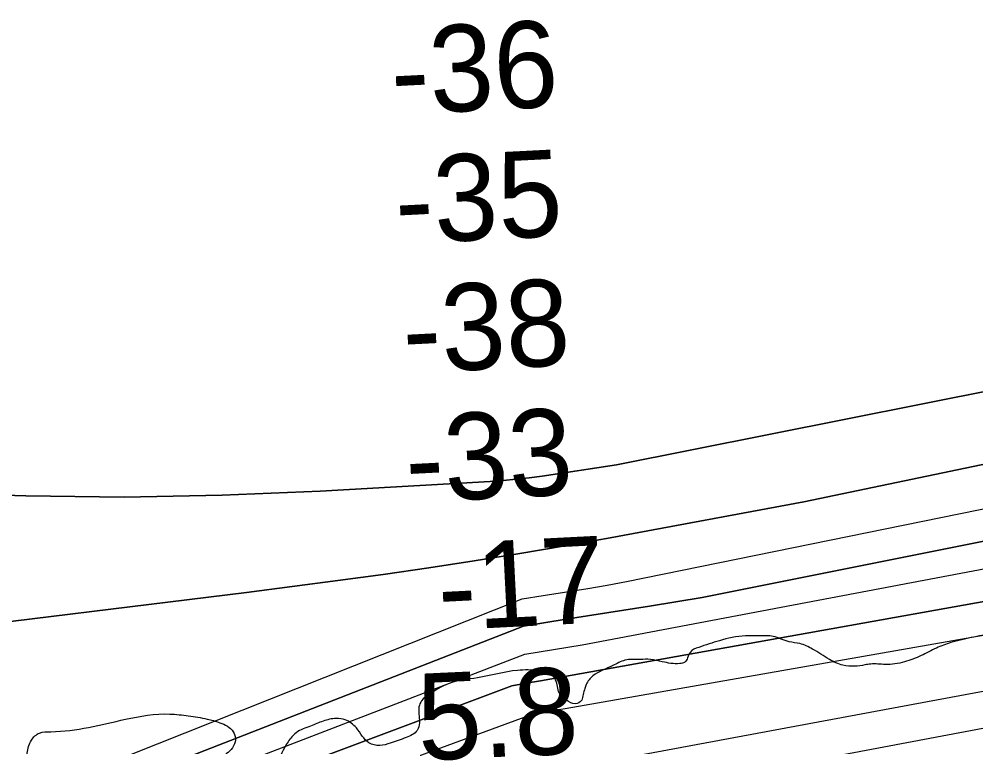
# Model space of a CAD drawing. Extents: x 3445503 to 3483459, y 540493 to 566012.
# Drawn here: x 3461717 to 3462457, y 550217 to 550780 of the extents above; entities that cross this region are included whole.
import ezdxf

# ---------------------------------------------------------------- set-up
doc = ezdxf.new("R2010")
doc.units = 0
for name, color, linetype in [('V-RIVR-EDGE', 7, 'Continuous'), ('V-RIVR-RANG', 7, 'Continuous'), ('V-TOPO-DPTH', 7, 'Continuous'), ('V-TOPO-MINR', 7, 'Continuous'), ('V-TOPO-WATR', 7, 'Continuous')]:
    doc.layers.add(name, color=color, linetype=linetype)

msp = doc.modelspace()

# ---------------------------------------------------------------- linework, layer by layer
at = {"layer": 'V-RIVR-EDGE'}
for points in [[(3464240.76, 550568.22), (3464194.17, 550562.43), (3464170.52, 550559.36), (3464160.09, 550560.08), (3464152.1, 550562.88), (3464144.1, 550559.77), (3464137.84, 550557.01), (3464132.61, 550553.54), (3464120.44, 550551.84), (3464111.75, 550549.77), (3464091.59, 550551.21), (3464071.09, 550554.74), (3464053.36, 550554.43), (3464011.29, 550553.84), (3463955.31, 550548.07), (3463935.83, 550543.95), (3463926.09, 550539.11), (3463922.24, 550531.47), (3463921.87, 550521.39), (3463920.11, 550511.66), (3463915.92, 550505.41), (3463903.4, 550501.97), (3463893.32, 550502.69), (3463886.03, 550507.57), (3463876.67, 550518.02), (3463871.82, 550526.73), (3463860.71, 550532.66), (3463854.46, 550531.98), (3463843.32, 550529.23), (3463836.02, 550528.9), (3463822.12, 550529.63), (3463812.04, 550532.09), (3463805.09, 550530.71), (3463800.56, 550526.9), (3463796.04, 550525.17), (3463792.21, 550525.18), (3463785.97, 550530.07), (3463777.63, 550533.91), (3463755.74, 550536.75), (3463735.23, 550537.84), (3463700.81, 550536.88), (3463663.61, 550531.76), (3463638.57, 550527.65), (3463632.65, 550525.23), (3463623.61, 550524.21), (3463615.62, 550525.62), (3463608.32, 550525.29), (3463599.27, 550522.88), (3463591.95, 550516.29), (3463587.08, 550514.57), (3463580.14, 550517.02), (3463569.72, 550522.26), (3463566.94, 550522.26), (3463563.11, 550519.84), (3463559.63, 550517.07), (3463551.28, 550516.39), (3463543.64, 550517.8), (3463539.47, 550521.29), (3463535.66, 550524.43), (3463531.49, 550525.48), (3463519.32, 550525.16), (3463508.2, 550524.15), (3463500.53, 550518.95), (3463474.8, 550516.23), (3463463.33, 550517.31), (3463452.21, 550516.64), (3463438.64, 550513.89), (3463430.99, 550511.48), (3463420.56, 550511.15), (3463410.13, 550511.18), (3463402.49, 550515.72), (3463395.9, 550519.56), (3463391.38, 550520.61), (3463385.13, 550520.98), (3463379.21, 550519.95), (3463372.6, 550516.84), (3463363.55, 550509.9), (3463354.14, 550504.02), (3463345.1, 550501.61), (3463333.62, 550497.46), (3463323.88, 550496.1), (3463316.23, 550496.81), (3463311.37, 550496.82), (3463301.28, 550495.11), (3463290.85, 550493.05), (3463275.2, 550490.31), (3463253.64, 550487.93), (3463230.69, 550485.9), (3463201.83, 550482.15), (3463171.58, 550478.75), (3463158.36, 550475.65), (3463147.22, 550471.85), (3463129.49, 550468.77), (3463117.67, 550468.8), (3463103.06, 550466.4), (3463077.33, 550462.99), (3463057.51, 550460.26), (3463023.42, 550453.39), (3462976.47, 550444.81), (3462928.47, 550432.76), (3462869.67, 550415.18), (3462853.67, 550410), (3462833.15, 550404.84), (3462827.24, 550405.2), (3462820.63, 550404.87), (3462811.59, 550404.55), (3462801.16, 550403.53), (3462795.59, 550398.68), (3462790.01, 550393.82), (3462786.52, 550387.92), (3462785.12, 550381.32), (3462781.98, 550377.85), (3462773.63, 550376.48), (3462765.98, 550375.81), (3462759.04, 550378.26), (3462750.36, 550384.88), (3462742.03, 550389.08), (3462735.08, 550391.87), (3462711.45, 550392.98), (3462677.71, 550386.45), (3462657.53, 550380.94), (3462643.26, 550372.98), (3462626.55, 550362.25), (3462614.01, 550351.85), (3462607.03, 550342.13), (3462601.8, 550335.89), (3462595.88, 550330.34), (3462589.61, 550327.92), (3462581.96, 550326.2), (3462575.36, 550326.91), (3462565.98, 550329.72), (3462554.17, 550333.92), (3462549.31, 550335.32), (3462542.01, 550334.64), (3462530.52, 550330.15), (3462505.46, 550317.7), (3462485.98, 550310.1), (3462462.67, 550303.9), (3462437.28, 550298.05), (3462426.14, 550293.91), (3462414.31, 550288.03), (3462401.43, 550283.19), (3462386.48, 550281.15), (3462375.36, 550281.52), (3462370.84, 550280.84), (3462362.84, 550279.81), (3462353.8, 550280.53), (3462343.39, 550285.08), (3462330.19, 550293.1), (3462320.47, 550297.3), (3462312.13, 550298.71), (3462299.98, 550302.91), (3462289.2, 550303.29), (3462278.42, 550303.31), (3462258.25, 550299.54), (3462242.25, 550294.36), (3462235.63, 550290.56), (3462231.44, 550282.92), (3462227.62, 550281.89), (3462214.06, 550283.31), (3462205.03, 550285.07), (3462197.03, 550285.09), (3462185.21, 550284.42), (3462175.81, 550280.28), (3462160.5, 550272.32), (3462155.27, 550265.73), (3462154.22, 550262.6), (3462152.82, 550258.08), (3462151.76, 550253.57), (3462146.89, 550250.8), (3462139.94, 550253.6), (3462134.39, 550259.17), (3462131.64, 550269.26), (3462126.44, 550274.14), (3462118.79, 550276.25), (3462102.11, 550276.63), (3462071.15, 550270.8), (3462048.55, 550266.34), (3462033.93, 550258.03), (3462028, 550253.18), (3462025.91, 550248.32), (3462025.89, 550242.76), (3462026.22, 550236.15), (3462024.47, 550230.24), (3462016.11, 550224.7), (3462003.75, 550220.36)], [(3462003.75, 550220.36), (3461995.59, 550218.5), (3461987.25, 550220.6), (3461977.55, 550232.1), (3461968.87, 550238.38), (3461961.92, 550239.44), (3461951.83, 550237.38), (3461942.09, 550233.58), (3461930.95, 550228.39), (3461924.68, 550221.45), (3461915.25, 550203.75), (3461912.11, 550199.93), (3461906.89, 550198.2), (3461903.06, 550195.43), (3461899.93, 550192.31), (3461893.98, 550179.12), (3461884.55, 550158.98), (3461876.18, 550149.26), (3461867.47, 550142.33), (3461855.29, 550137.15), (3461827.11, 550127.83), (3461811.47, 550129.26), (3461801.39, 550128.24), (3461788.17, 550124.11), (3461754.41, 550110.28), (3461738.75, 550103.37), (3461726.23, 550099.92), (3461715.1, 550099.26), (3461705.71, 550096.15), (3461691.09, 550090.62)], [(3461782.02, 550168.62), (3461757, 550174.24), (3461737.21, 550180.9), (3461728.88, 550187.52), (3461727.15, 550193.09), (3461723.03, 550212.56), (3461726.18, 550222.64), (3461732.46, 550228.18), (3461741.15, 550229.21), (3461798.88, 550238.8), (3461833.3, 550242.88), (3461847.55, 550241.46), (3461862.15, 550238.99), (3461871.88, 550236.18), (3461882.29, 550229.2), (3461884.01, 550222.94), (3461883.31, 550219.82), (3461879.47, 550214.26), (3461869.37, 550207.34)]]:
    msp.add_spline(points, degree=3, dxfattribs=at)
at = {"layer": 'V-TOPO-DPTH'}
for points in [[(3460826.61, 549947.36), (3461361.19, 550029.12), (3461371.44, 550030.75), (3461381.68, 550032.46), (3461391.9, 550034.29), (3461402.1, 550036.21), (3462106.66, 550310.78), (3462139.67, 550316.11), (3462172.7, 550321.33), (3462204.17, 550326.22), (3462244.98, 550332.83), (3462841.69, 550452.28), (3463001.94, 550483.79), (3463015.58, 550486.53), (3463029.21, 550489.34), (3463042.81, 550492.26), (3463056.4, 550495.25), (3463082.34, 550501.06), (3463096.66, 550504.41), (3463110.93, 550507.93), (3463641.78, 550595.69), (3463666.23, 550597.32), (3463690.7, 550598.76), (3463850.95, 550607.3)], [(3463850.95, 550607.3), (3463690.7, 550598.76), (3463666.23, 550597.32), (3463641.78, 550595.69), (3463110.93, 550507.93), (3463096.66, 550504.41), (3463082.34, 550501.06), (3463056.4, 550495.25), (3463042.81, 550492.26), (3463029.21, 550489.34), (3463015.58, 550486.53), (3463001.94, 550483.79), (3462841.69, 550452.28), (3462244.98, 550332.83), (3462204.17, 550326.22), (3462172.7, 550321.33), (3462139.67, 550316.11), (3462106.66, 550310.78), (3461402.1, 550036.21), (3461391.9, 550034.29), (3461381.68, 550032.46), (3461371.44, 550030.75), (3461361.19, 550029.12), (3460826.61, 549947.36)], [(3463007.24, 550600.48), (3462178.76, 550435.51), (3462121.15, 550426.86), (3462111.16, 550425.5), (3462101.14, 550424.32), (3462091.1, 550423.42), (3462081.04, 550422.71), (3461949.53, 550415.25), (3461873.7, 550412.14), (3461797.86, 550410.6), (3461722.01, 550411.43), (3461646.15, 550413.83), (3461371.47, 550426.82), (3461359.67, 550427.42), (3461347.87, 550428.08), (3461336.08, 550428.82), (3461324.3, 550429.61), (3461297.72, 550431.5), (3461272.66, 550433.43), (3461247.62, 550435.58), (3461222.6, 550438.03), (3461197.61, 550440.69)], [(3463007.24, 550600.48), (3462178.76, 550435.51), (3462121.15, 550426.86), (3462111.16, 550425.5), (3462101.14, 550424.32), (3462091.1, 550423.42), (3462081.04, 550422.71), (3461949.53, 550415.25), (3461873.7, 550412.14), (3461797.86, 550410.6), (3461722.01, 550411.43), (3461646.15, 550413.83), (3461371.47, 550426.82), (3461359.67, 550427.42), (3461347.87, 550428.08), (3461336.08, 550428.82), (3461324.3, 550429.61), (3461297.72, 550431.5), (3461272.66, 550433.43), (3461247.62, 550435.58), (3461222.6, 550438.03), (3461197.61, 550440.69)], [(3460796.68, 549887), (3461333.7, 549993.24), (3461359, 549997.61), (3461384.27, 550002.09), (3461409.51, 550006.76), (3462097.68, 550264.71), (3462108.77, 550266.64), (3462119.87, 550268.5), (3462864.92, 550401.86), (3462898.89, 550408.81), (3462949.81, 550419.38), (3462966.81, 550422.78), (3462983.82, 550426.13), (3462991.05, 550427.53), (3463642.04, 550570.24), (3463653.7, 550570.91), (3463665.37, 550571.48), (3464200.45, 550593.79)], [(3464200.45, 550593.79), (3463665.37, 550571.48), (3463653.7, 550570.91), (3463642.04, 550570.24), (3462991.05, 550427.53), (3462983.82, 550426.13), (3462966.81, 550422.78), (3462949.81, 550419.38), (3462898.89, 550408.81), (3462864.92, 550401.86), (3462119.87, 550268.5), (3462108.77, 550266.64), (3462097.68, 550264.71), (3461409.51, 550006.76), (3461384.27, 550002.09), (3461359, 549997.61), (3461333.7, 549993.24), (3460796.68, 549887)], [(3459211.38, 549345.72), (3459924.71, 549586.06), (3459936.94, 549589.12), (3460800.63, 549811.2), (3461414.15, 549976.77), (3461441.4, 549981.97), (3462062.16, 550182.04), (3462087.24, 550188.76), (3462112.44, 550194.95), (3462137.83, 550200.35), (3463061.3, 550371.99), (3463612.81, 550520.65), (3463627.71, 550525.32), (3463642.71, 550529.62), (3463657.86, 550533.37), (3463673.11, 550536.73), (3463688.48, 550539.38), (3463703.91, 550541.45), (3463719.44, 550542.63), (3463735.03, 550543.24)], [(3462841.11, 550514.77), (3462323.66, 550406.99), (3462173.91, 550379.16), (3462138.91, 550372.86), (3462103.86, 550366.84), (3462068.74, 550361.22), (3462033.58, 550355.87), (3461998.36, 550350.85), (3461963.13, 550345.99), (3461927.86, 550341.36), (3461892.57, 550336.89), (3461380.43, 550273.82), (3461370.85, 550272.55), (3461361.3, 550271.17), (3461351.77, 550269.6), (3461342.26, 550267.92), (3461286.68, 550257.57), (3461267.79, 550253.44), (3461249.13, 550248.55), (3461230.8, 550242.51), (3461212.7, 550235.71), (3461194.82, 550228.22)], [(3461194.82, 550228.22), (3461212.7, 550235.71), (3461230.8, 550242.51), (3461249.13, 550248.55), (3461267.79, 550253.44), (3461286.68, 550257.57), (3461342.26, 550267.92), (3461351.77, 550269.6), (3461361.3, 550271.17), (3461370.85, 550272.55), (3461380.43, 550273.82), (3461892.57, 550336.89), (3461927.86, 550341.36), (3461963.13, 550345.99), (3461998.36, 550350.85), (3462033.58, 550355.87), (3462068.74, 550361.22), (3462103.86, 550366.84), (3462138.91, 550372.86), (3462173.91, 550379.16), (3462323.66, 550406.99), (3462841.11, 550514.77)]]:
    msp.add_lwpolyline(points, dxfattribs=at)
at = {"layer": 'V-TOPO-MINR'}
for points in [[(3460826.61, 549947.36), (3461361.19, 550029.12), (3461371.44, 550030.75), (3461381.68, 550032.46), (3461391.9, 550034.29), (3461402.1, 550036.21), (3462106.66, 550310.78), (3462139.67, 550316.11), (3462172.7, 550321.33), (3462204.17, 550326.22), (3462244.98, 550332.83), (3462841.69, 550452.28), (3463001.94, 550483.79), (3463015.58, 550486.53), (3463029.21, 550489.34), (3463042.81, 550492.26), (3463056.4, 550495.25), (3463082.34, 550501.06), (3463096.66, 550504.41), (3463110.93, 550507.93), (3463641.78, 550595.69), (3463666.23, 550597.32), (3463690.7, 550598.76), (3463850.95, 550607.3)], [(3460819.02, 549919.51), (3461347.41, 550011.27), (3461365.2, 550014.22), (3461382.97, 550017.29), (3461400.71, 550020.52), (3461418.43, 550023.87), (3462107.7, 550289.11), (3462129.95, 550292.77), (3462152.21, 550296.35), (3463030.72, 550462.58), (3463057.52, 550468.3), (3463084.29, 550474.15), (3463139.15, 550486.38), (3463641.91, 550582.76), (3463659.88, 550583.88), (3463677.85, 550584.84), (3463985.31, 550599.4)], [(3461197.61, 550440.69), (3461222.6, 550438.03), (3461247.62, 550435.58), (3461272.66, 550433.43), (3461297.72, 550431.5), (3461324.3, 550429.61), (3461336.08, 550428.82), (3461347.87, 550428.08), (3461359.67, 550427.42), (3461371.47, 550426.82), (3461646.15, 550413.83), (3461722.01, 550411.43), (3461797.86, 550410.6), (3461873.7, 550412.14), (3461949.53, 550415.25), (3462081.04, 550422.71), (3462091.1, 550423.42), (3462101.14, 550424.32), (3462111.16, 550425.5), (3462121.15, 550426.86), (3462178.76, 550435.51), (3463007.24, 550600.48)], [(3460773.79, 549852.53), (3461385.57, 549986.88), (3461418.29, 549993.01), (3461451, 549999.24), (3462105.17, 550239.69), (3462107.58, 550240.52), (3462110, 550241.3), (3462112.44, 550242.02), (3462114.9, 550242.69), (3462117.37, 550243.29), (3462119.85, 550243.85), (3462122.35, 550244.34), (3462124.86, 550244.78), (3462129.36, 550245.52), (3462132.54, 550246.04), (3462135.72, 550246.56), (3462138.9, 550247.09), (3463034.12, 550404.13), (3463040.52, 550405.37), (3463046.91, 550406.63), (3463653.21, 550558.59), (3464432.27, 550586.79)], [(3459211.38, 549345.72), (3459924.71, 549586.06), (3459936.94, 549589.12), (3460800.63, 549811.2), (3461414.15, 549976.77), (3461441.4, 549981.97), (3462062.16, 550182.04), (3462087.24, 550188.76), (3462112.44, 550194.95), (3462137.83, 550200.35), (3463061.3, 550371.99), (3463612.81, 550520.65), (3463627.71, 550525.32), (3463642.71, 550529.62), (3463657.86, 550533.37), (3463673.11, 550536.73), (3463688.48, 550539.38), (3463703.91, 550541.45), (3463719.44, 550542.63), (3463735.03, 550543.24)], [(3460771.44, 549971.49), (3461212, 550024.88), (3461254.12, 550030.39), (3461296.23, 550036.04), (3461375.03, 550046.79), (3461377.72, 550047.18), (3461380.4, 550047.6), (3461383.08, 550048.07), (3461385.75, 550048.56), (3461402.47, 550051.81), (3461404.55, 550052.33), (3461406.56, 550053), (3461410.37, 550054.91), (3461411.7, 550056.22), (3462105.63, 550332), (3462122.1, 550334.61), (3462138.59, 550337.17), (3462141.52, 550337.62), (3462156.53, 550340.02), (3462171.51, 550342.55), (3462186.46, 550345.27), (3463031.03, 550517.1)], [(3461194.82, 550228.22), (3461212.7, 550235.71), (3461230.8, 550242.51), (3461249.13, 550248.55), (3461267.79, 550253.44), (3461286.68, 550257.57), (3461342.26, 550267.92), (3461351.77, 550269.6), (3461361.3, 550271.17), (3461370.85, 550272.55), (3461380.43, 550273.82), (3461892.57, 550336.89), (3461927.86, 550341.36), (3461963.13, 550345.99), (3461998.36, 550350.85), (3462033.58, 550355.87), (3462068.74, 550361.22), (3462103.86, 550366.84), (3462138.91, 550372.86), (3462173.91, 550379.16), (3462323.66, 550406.99), (3462841.11, 550514.77)], [(3459155.64, 549293.25), (3459905.81, 549540.06), (3459920.2, 549545.16), (3459934.63, 549550.14), (3459949.08, 549555.05), (3460803.93, 549764.42), (3461388.2, 549956.36), (3461392.75, 549957.21), (3461397.29, 549958.07), (3462102.29, 550164.56), (3462113.64, 550166.95), (3462125.07, 550168.97), (3462136.55, 550170.74), (3463026.5, 550338.47), (3463037.8, 550339.99), (3463049.11, 550341.47), (3463060.43, 550342.92), (3463631.14, 550468.86), (3463643.23, 550470.52), (3463655.39, 550471.51), (3463667.59, 550472.05), (3464480.31, 550485.96)]]:
    msp.add_lwpolyline(points, dxfattribs=at)
at = {"layer": 'V-TOPO-WATR'}
msp.add_lwpolyline([(3460796.68, 549887), (3461333.7, 549993.24), (3461359, 549997.61), (3461384.27, 550002.09), (3461409.51, 550006.76), (3462097.68, 550264.71), (3462108.77, 550266.64), (3462119.87, 550268.5), (3462864.92, 550401.86), (3462898.89, 550408.81), (3462949.81, 550419.38), (3462966.81, 550422.78), (3462983.82, 550426.13), (3462991.05, 550427.53), (3463642.04, 550570.24), (3463653.7, 550570.91), (3463665.37, 550571.48), (3464200.45, 550593.79)], dxfattribs=at)

# ---------------------------------------------------------------- texts
at = {"layer": 'V-RIVR-RANG'}
for s, rotation, p in [('-36', 2.89644, (3462005.56, 550706.07)), ('-35', 2.89644, (3462008.79, 550606.1)), ('-38', 2.89644, (3462014.65, 550506.27)), ('-33', 2.89644, (3462016.82, 550406.25)), ('-17', 2.89644, (3462041.9, 550307.39)), ('5.8', 2.60833, (3462025.98, 550206.89))]:
    msp.add_text(s, height=67, rotation=rotation, dxfattribs=at).set_placement(p)

doc.saveas('drawing.dxf')
